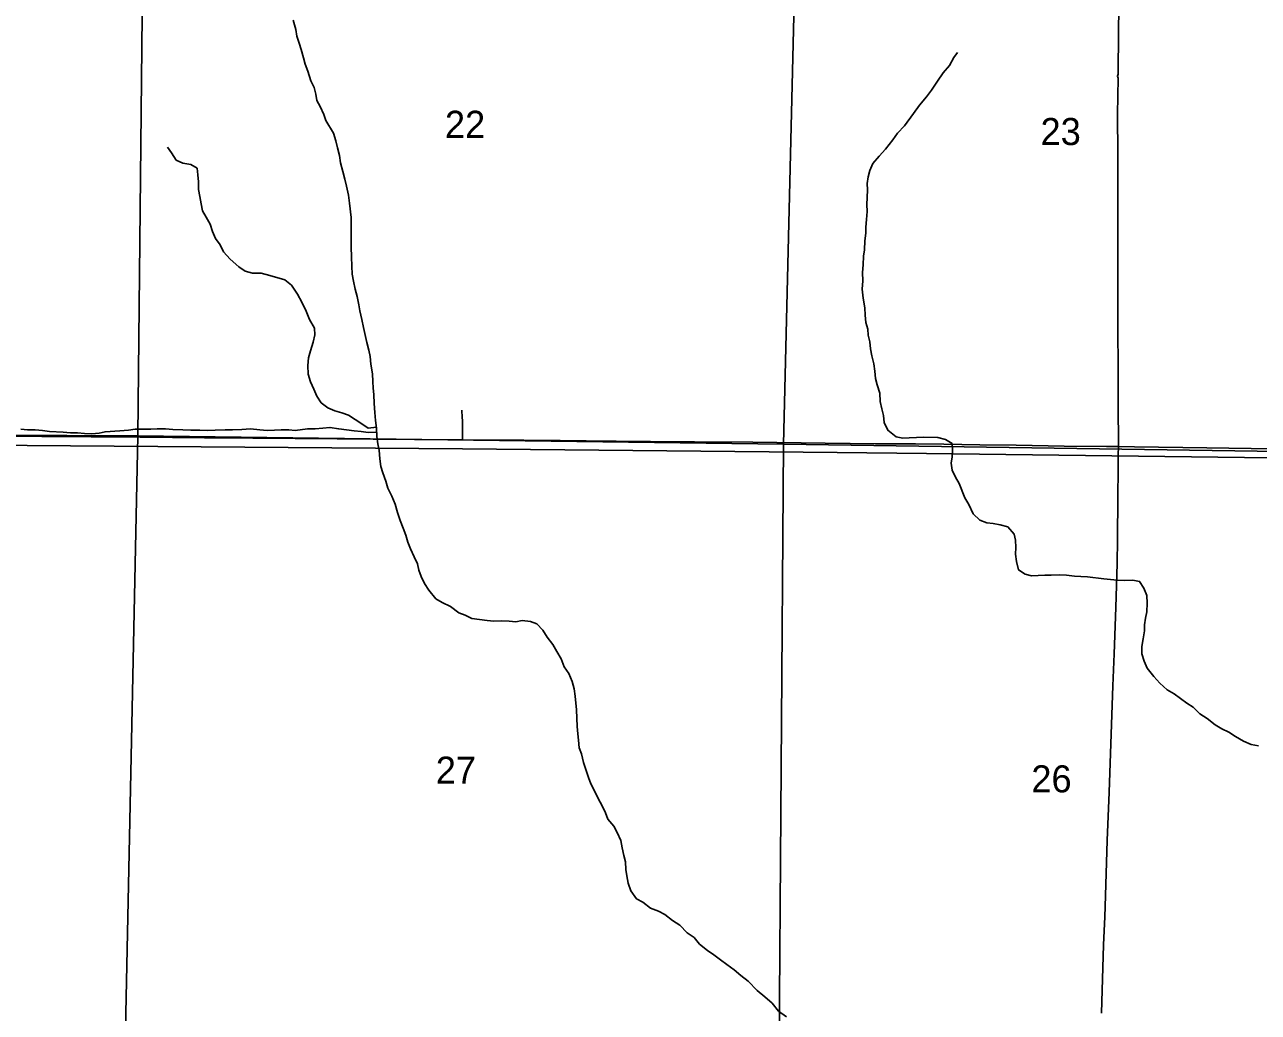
# Model space of a CAD drawing. Extents: x 1584893 to 1934202, y 663575 to 1091909.
# Drawn here: x 1760284 to 1770359, y 938155 to 946219 of the extents above; entities that cross this region are included whole.
import ezdxf

# ---------------------------------------------------------------- set-up
doc = ezdxf.new("R2010")
doc.units = 0
for name, color, linetype in [('GM_X_Minor_River', 7, 'Continuous'), ('GM_X_Rail_Line', 7, 'Continuous'), ('GM_X_Section', 7, 'Continuous'), ('GM_X_Section_Text', 7, 'Continuous'), ('GM_X_State_Route', 7, 'Continuous'), ('GM_X_Township_Road', 7, 'Continuous')]:
    doc.layers.add(name, color=color, linetype=linetype)

msp = doc.modelspace()

# ---------------------------------------------------------------- linework, layer by layer
at = {"layer": 'GM_X_Minor_River'}
for points in [[(1764551, 941219), (1764514, 941276), (1764467, 941327), (1764415, 941345), (1764347, 941353), (1764295, 941344), (1764241, 941350), (1764180, 941352), (1764114, 941349), (1764062, 941354), (1763936, 941370), (1763881, 941399), (1763829, 941418), (1763760, 941469), (1763693, 941500), (1763642, 941531), (1763583, 941602), (1763548, 941657), (1763521, 941713), (1763502, 941766), (1763491, 941818), (1763464, 941874), (1763435, 941939), (1763414, 941995), (1763397, 942050), (1763374, 942108), (1763349, 942171), (1763328, 942237), (1763309, 942303), (1763282, 942370), (1763249, 942436), (1763234, 942493), (1763208, 942561), (1763192, 942612), (1763185, 942674), (1763179, 942746), (1763168, 942798), (1763160, 942856), (1763158, 942924), (1763149, 942987), (1763142, 943053), (1763139, 943125), (1763134, 943199), (1763129, 943251), (1763128, 943305), (1763123, 943369), (1763110, 943446), (1763105, 943510), (1763094, 943562), (1763079, 943624), (1763063, 943697), (1763051, 943747), (1763037, 943813), (1763020, 943882), (1763013, 943932), (1762998, 944000), (1762983, 944060), (1762968, 944125), (1762959, 944183), (1762956, 944247), (1762953, 944323), (1762951, 944403), (1762951, 944461), (1762949, 944527), (1762951, 944645), (1762936, 944762), (1762928, 944826), (1762913, 944900), (1762898, 944957), (1762883, 945019), (1762864, 945091), (1762855, 945151), (1762838, 945214), (1762825, 945270), (1762806, 945334), (1762744, 945436), (1762727, 945486), (1762698, 945550), (1762669, 945601), (1762662, 945651), (1762647, 945705), (1762622, 945760), (1762595, 945838), (1762574, 945897), (1762561, 945949), (1762542, 946016), (1762525, 946068), (1762506, 946124), (1762497, 946180), (1762476, 946255)], [(1768193, 942147), (1768141, 942152), (1768084, 942173), (1768029, 942224), (1767994, 942302), (1767961, 942355), (1767915, 942472), (1767886, 942525), (1767857, 942583), (1767850, 942639), (1767859, 942691), (1767862, 942745), (1767859, 942799), (1767803, 942832), (1767740, 942849), (1767622, 942851), (1767568, 942848), (1767508, 942845), (1767454, 942844), (1767400, 942853), (1767333, 942908), (1767302, 942971), (1767297, 943029), (1767284, 943083), (1767269, 943142), (1767268, 943210), (1767246, 943278), (1767233, 943330), (1767228, 943391), (1767219, 943451), (1767202, 943515), (1767191, 943571), (1767186, 943630), (1767171, 943684), (1767169, 943734), (1767154, 943786), (1767149, 943848), (1767144, 943906), (1767132, 943985), (1767123, 944059), (1767130, 944127), (1767127, 944195), (1767132, 944257), (1767135, 944329), (1767142, 944381), (1767145, 944453), (1767152, 944517), (1767153, 944567), (1767158, 944627), (1767163, 944693), (1767162, 944751), (1767163, 944809), (1767168, 944871), (1767163, 944923), (1767172, 944977), (1767185, 945029), (1767210, 945086), (1767263, 945145), (1767313, 945203), (1767373, 945278), (1767411, 945333), (1767468, 945392), (1767542, 945495), (1767591, 945562), (1767648, 945631), (1767689, 945684), (1767738, 945758), (1767785, 945825), (1767836, 945886), (1767871, 945950), (1767901, 945991)], [(1763156, 942934), (1763090, 942924), (1763036, 942961), (1762983, 942996), (1762928, 943030), (1762874, 943049), (1762817, 943066), (1762759, 943091), (1762706, 943132), (1762669, 943187), (1762644, 943244), (1762617, 943302), (1762600, 943366), (1762597, 943437), (1762602, 943500), (1762617, 943556), (1762640, 943626), (1762653, 943686), (1762650, 943742), (1762611, 943813), (1762583, 943881), (1762546, 943952), (1762513, 944020), (1762464, 944091), (1762409, 944136), (1762286, 944170), (1762214, 944190), (1762145, 944191), (1762085, 944206), (1762034, 944243), (1761961, 944304), (1761908, 944363), (1761879, 944422), (1761842, 944472), (1761817, 944529), (1761798, 944591), (1761765, 944648), (1761736, 944700), (1761725, 944757), (1761714, 944817), (1761703, 944873), (1761702, 944935), (1761697, 944993), (1761692, 945047), (1761640, 945076), (1761576, 945087), (1761521, 945114), (1761484, 945173), (1761449, 945218)], [(1763159, 942891), (1763089, 942888), (1763033, 942897), (1762974, 942902), (1762848, 942918), (1762776, 942931), (1762720, 942924), (1762656, 942919), (1762593, 942920), (1762493, 942906), (1762441, 942911), (1762379, 942912), (1762325, 942909), (1762265, 942906), (1762205, 942911), (1762129, 942918), (1762056, 942913), (1761982, 942911), (1761920, 942912), (1761840, 942907), (1761776, 942906), (1761714, 942909), (1761640, 942907), (1761574, 942910), (1761495, 942913), (1761435, 942920), (1761367, 942919), (1761313, 942916), (1761259, 942917), (1761187, 942916), (1761131, 942907), (1761061, 942903), (1760941, 942895), (1760891, 942885), (1760833, 942878), (1760771, 942882), (1760714, 942887), (1760658, 942886), (1760598, 942893), (1760486, 942898), (1760429, 942905), (1760369, 942911), (1760307, 942912), (1760253, 942917)], [(1770361, 940330), (1770301, 940341), (1770238, 940370), (1770171, 940407), (1770119, 940442), (1770060, 940471), (1770006, 940502), (1769941, 940553), (1769880, 940592), (1769827, 940647), (1769776, 940680), (1769723, 940717), (1769671, 940756), (1769614, 940787), (1769553, 940844), (1769506, 940897), (1769451, 940966), (1769426, 941023), (1769407, 941081), (1769406, 941141), (1769419, 941205), (1769428, 941269), (1769429, 941319), (1769438, 941373), (1769447, 941425), (1769450, 941497), (1769447, 941559), (1769424, 941617), (1769389, 941674), (1769333, 941683), (1769267, 941682), (1769206, 941683), (1769152, 941690), (1769096, 941695), (1768964, 941711), (1768909, 941714), (1768857, 941717), (1768793, 941724), (1768731, 941727), (1768667, 941724), (1768615, 941725), (1768561, 941722), (1768505, 941719), (1768454, 941732), (1768400, 941767), (1768384, 941835), (1768375, 941896), (1768379, 941950), (1768376, 942010), (1768365, 942060), (1768312, 942119), (1768251, 942136), (1768193, 942147)], [(1766504, 938118), (1766441, 938166), (1766388, 938229), (1766327, 938282), (1766266, 938333), (1766191, 938410), (1766132, 938457), (1766079, 938502), (1766018, 938547), (1765965, 938584), (1765911, 938625), (1765860, 938660), (1765795, 938713), (1765750, 938766), (1765693, 938803), (1765634, 938866), (1765573, 938905), (1765511, 938954), (1765460, 938981), (1765395, 939006), (1765331, 939054), (1765280, 939082), (1765233, 939147), (1765212, 939210), (1765201, 939270), (1765192, 939322), (1765191, 939384), (1765178, 939435), (1765163, 939499), (1765152, 939559), (1765123, 939624), (1765094, 939676), (1765047, 939733), (1765026, 939784), (1765001, 939842), (1764968, 939901), (1764941, 939957), (1764908, 940020), (1764887, 940072), (1764868, 940129), (1764847, 940195), (1764830, 940265), (1764813, 940316), (1764806, 940378), (1764801, 940428), (1764796, 940488), (1764793, 940558), (1764790, 940624), (1764780, 940737), (1764771, 940797), (1764756, 940855), (1764727, 940922), (1764690, 940976), (1764666, 941041), (1764631, 941100), (1764598, 941158), (1764551, 941219)]]:
    msp.add_lwpolyline(points, dxfattribs=at)
at = {"layer": 'GM_X_Rail_Line'}
msp.add_lwpolyline([(1759945, 942787), (1763859, 942756), (1766919, 942727), (1767649, 942719), (1771759, 942665), (1773575, 942642), (1774777, 942625), (1775637, 942614), (1776851, 942599), (1777963, 942588), (1779701, 942579)], dxfattribs=at)
at = {"layer": 'GM_X_Section'}
for points in [[(1756130, 948165), (1761263, 948146), (1761209, 942861), (1755981, 942886)], [(1761263, 948146), (1766608, 948095), (1766481, 942794), (1761209, 942861)], [(1766608, 948095), (1771900, 948032), (1771824, 942715), (1766481, 942794)], [(1755981, 942886), (1761209, 942861), (1761100, 937622), (1761097, 937566), (1755912, 937626)], [(1761209, 942861), (1766481, 942794), (1766444, 937515), (1761100, 937622)], [(1766481, 942794), (1771824, 942715), (1771650, 937464), (1766444, 937515)]]:
    msp.add_lwpolyline(points, close=True, dxfattribs=at)
at = {"layer": 'GM_X_State_Route'}
for points in [[(1769077, 938149), (1769095, 938707), (1769105, 938936), (1769108, 939018), (1769113, 939198), (1769125, 939559), (1769140, 939952), (1769171, 940820), (1769181, 941083), (1769194, 941460), (1769206, 941820), (1769209, 942017), (1769212, 942361), (1769214, 942591), (1769215, 942706), (1769217, 942774), (1769216, 942809), (1769214, 943091), (1769213, 943419), (1769212, 943731), (1769212, 943977), (1769212, 944387), (1769210, 944683), (1769210, 945159), (1769209, 945487), (1769213, 945782), (1769208, 945799), (1769213, 945815), (1769213, 945881), (1769216, 946094), (1769219, 946422)], [(1759816, 942863), (1760423, 942857), (1761227, 942851), (1761752, 942846), (1762146, 942843), (1762835, 942837), (1763130, 942836), (1763803, 942830), (1763858, 942830), (1764114, 942828), (1764360, 942826), (1764656, 942824), (1764869, 942821), (1765115, 942818), (1765394, 942817), (1765755, 942814), (1766231, 942810), (1766821, 942803), (1767232, 942798), (1767560, 942796), (1767789, 942793), (1768085, 942788), (1768380, 942785), (1768774, 942779), (1769118, 942775), (1769217, 942774), (1769348, 942773), (1769938, 942764), (1770480, 942755)]]:
    msp.add_lwpolyline(points, dxfattribs=at)
at = {"layer": 'GM_X_Township_Road'}
for points in [[(1763857, 943013), (1763854, 943071)], [(1763858, 942830), (1763858, 942851), (1763859, 942937), (1763859, 942987), (1763857, 943013)]]:
    msp.add_lwpolyline(points, dxfattribs=at)

# ---------------------------------------------------------------- texts
at = {"layer": 'GM_X_Section_Text'}
for s, p in [('22', (1763716, 945295)), ('23', (1768580, 945236)), ('27', (1763641, 940022)), ('26', (1768505, 939951))]:
    msp.add_text(s, height=221, rotation=0, dxfattribs=at).set_placement(p)

doc.saveas('drawing.dxf')
